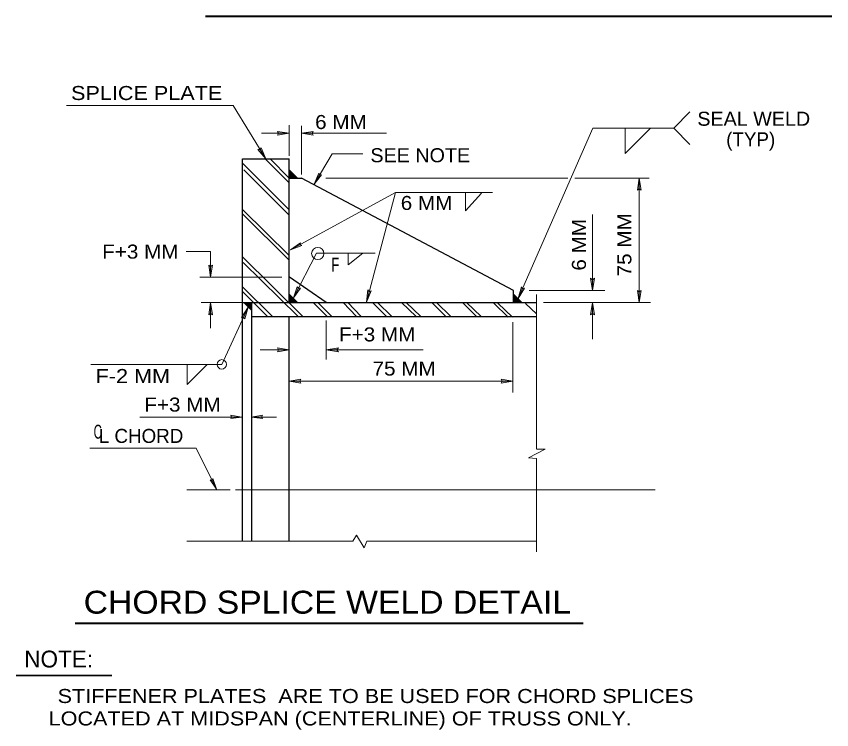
# Model space of a CAD drawing. Extents: x 312601.858 to 312602.699, y 144420.109 to 144420.704.
# Drawn here: x 312602.1021 to 312602.2763, y 144420.3916 to 144420.5441 of the extents above; entities that cross this region are included whole.
import ezdxf
from ezdxf.enums import TextEntityAlignment as Align

# ---------------------------------------------------------------- set-up
doc = ezdxf.new("R2010")
doc.units = 0
doc.header["$LTSCALE"] = 0.0012
doc.linetypes.add('DOT_DASHED', pattern=[7.7, 5, -1.2, 0.3, -1.2])
for name, color, linetype, lineweight in [('1', 7, 'Continuous', 25), ('2', 7, 'Continuous', 13), ('39', 7, 'Continuous', 13)]:
    doc.layers.add(name, color=color, linetype=linetype, lineweight=lineweight)

msp = doc.modelspace()

# ---------------------------------------------------------------- hatches: boundary and pattern name
at = {"layer": '2'}
for points in [[(312602.1604, 144420.5095), (312602.1604, 144420.5113), (312602.1622, 144420.5095)], [(312602.1604, 144420.4829), (312602.1604, 144420.4847), (312602.1622, 144420.4829)], [(312602.2083, 144420.4829), (312602.2083, 144420.4847), (312602.2101, 144420.4829)], [(312602.1524, 144420.4812), (312602.1507, 144420.4829), (312602.1524, 144420.4829)]]:
    msp.add_hatch(color=256, dxfattribs=at).paths.add_polyline_path(points)
at = {"layer": '39'}
for points in [[(312602.1581, 144420.5191), (312602.1579, 144420.5195), (312602.1604, 144420.5191), (312602.1579, 144420.5187)], [(312602.1581, 144420.5191), (312602.1579, 144420.5195), (312602.1604, 144420.5191), (312602.1579, 144420.5187)], [(312602.1653, 144420.5191), (312602.1655, 144420.5187), (312602.163, 144420.5191), (312602.1655, 144420.5195)], [(312602.1542, 144420.5156), (312602.1544, 144420.516), (312602.1554, 144420.5136), (312602.1537, 144420.5156)], [(312602.1669, 144420.5102), (312602.1673, 144420.5102), (312602.1657, 144420.5082), (312602.1667, 144420.5106)], [(312602.2352, 144420.5072), (312602.2348, 144420.5069), (312602.2352, 144420.5095), (312602.2356, 144420.5069)], [(312602.2352, 144420.5072), (312602.2348, 144420.5069), (312602.2352, 144420.5095), (312602.2356, 144420.5069)], [(312602.1627, 144420.4953), (312602.1631, 144420.4951), (312602.1607, 144420.4942), (312602.1628, 144420.4957)], [(312602.1436, 144420.4906), (312602.144, 144420.4909), (312602.1436, 144420.4883), (312602.1432, 144420.4909)], [(312602.1436, 144420.4906), (312602.144, 144420.4909), (312602.1436, 144420.4883), (312602.1432, 144420.4909)], [(312602.2252, 144420.4878), (312602.2256, 144420.4881), (312602.2252, 144420.4855), (312602.2248, 144420.4881)], [(312602.1624, 144420.486), (312602.1628, 144420.486), (312602.1613, 144420.4839), (312602.1621, 144420.4863)], [(312602.2102, 144420.4859), (312602.2107, 144420.486), (312602.2093, 144420.4838), (312602.21, 144420.4863)], [(312602.1775, 144420.4852), (312602.1779, 144420.4854), (312602.1769, 144420.483), (312602.1772, 144420.4856)], [(312602.2352, 144420.4852), (312602.2356, 144420.4855), (312602.2352, 144420.4829), (312602.2348, 144420.4855)], [(312602.1436, 144420.4806), (312602.1432, 144420.4803), (312602.1436, 144420.4829), (312602.144, 144420.4803)], [(312602.2252, 144420.4806), (312602.2248, 144420.4803), (312602.2252, 144420.4829), (312602.2256, 144420.4803)], [(312602.1506, 144420.4798), (312602.1502, 144420.4797), (312602.1516, 144420.4819), (312602.1509, 144420.4794)], [(312602.1581, 144420.4728), (312602.1579, 144420.4732), (312602.1604, 144420.4728), (312602.1579, 144420.4724)], [(312602.1581, 144420.4728), (312602.1579, 144420.4732), (312602.1604, 144420.4728), (312602.1579, 144420.4724)], [(312602.1706, 144420.4728), (312602.1709, 144420.4724), (312602.1683, 144420.4728), (312602.1709, 144420.4732)], [(312602.1627, 144420.4661), (312602.1629, 144420.4657), (312602.1604, 144420.4661), (312602.1629, 144420.4665)], [(312602.1627, 144420.4661), (312602.1629, 144420.4657), (312602.1604, 144420.4661), (312602.1629, 144420.4665)], [(312602.2059, 144420.4661), (312602.2057, 144420.4665), (312602.2082, 144420.4661), (312602.2057, 144420.4657)], [(312602.1481, 144420.4584), (312602.1479, 144420.4588), (312602.1503, 144420.4584), (312602.1479, 144420.4581)], [(312602.1481, 144420.4584), (312602.1479, 144420.4588), (312602.1503, 144420.4584), (312602.1479, 144420.4581)], [(312602.1545, 144420.4584), (312602.1547, 144420.4581), (312602.1523, 144420.4584), (312602.1547, 144420.4588)], [(312602.1439, 144420.4449), (312602.1441, 144420.4453), (312602.1449, 144420.443), (312602.1435, 144420.445)], [(312602.1439, 144420.4449), (312602.1441, 144420.4453), (312602.1449, 144420.443), (312602.1435, 144420.445)]]:
    msp.add_hatch(color=256, dxfattribs=at).paths.add_polyline_path(points)

# ---------------------------------------------------------------- linework, layer by layer
at = {"layer": '1'}
for p, q in [((312602.1604, 144420.4829), (312602.1604, 144420.5136)), ((312602.1604, 144420.5095), (312602.163, 144420.5095)), ((312602.2083, 144420.4855), (312602.163, 144420.5095)), ((312602.1683, 144420.4829), (312602.1605, 144420.4883)), ((312602.2083, 144420.4829), (312602.2083, 144420.4855)), ((312602.1504, 144420.4829), (312602.2132, 144420.4829)), ((312602.1524, 144420.4319), (312602.1524, 144420.4829)), ((312602.1524, 144420.4799), (312602.2132, 144420.4799)), ((312602.1604, 144420.4319), (312602.1604, 144420.4799))]:
    msp.add_line(p, q, dxfattribs=at)
msp.add_lwpolyline([(312602.1504, 144420.4319), (312602.1504, 144420.5136), (312602.1604, 144420.5136)], dxfattribs=at)
at = {"layer": '2', "lineweight": 40}
for p, q in [((312602.1425, 144420.5441), (312602.2763, 144420.5441)), ((312602.1147, 144420.4144), (312602.2232, 144420.4144))]:
    msp.add_line(p, q, dxfattribs=at)
at = {"layer": '2'}
for p, q in [((312602.1484, 144420.525), (312602.1128, 144420.525)), ((312602.1484, 144420.525), (312602.1554, 144420.5136)), ((312602.2426, 144420.5202), (312602.246, 144420.5237)), ((312602.1604, 144420.5143), (312602.1604, 144420.5208)), ((312602.163, 144420.5103), (312602.163, 144420.5207)), ((312602.1545, 144420.5191), (312602.1604, 144420.5191)), ((312602.163, 144420.5191), (312602.1812, 144420.5191)), ((312602.2093, 144420.4838), (312602.2253, 144420.5202)), ((312602.2253, 144420.5202), (312602.2426, 144420.5202)), ((312602.2322, 144420.5148), (312602.2322, 144420.5202)), ((312602.2322, 144420.5148), (312602.2376, 144420.5202)), ((312602.2426, 144420.5202), (312602.246, 144420.5167)), ((312602.1553, 144420.5136), (312602.1604, 144420.5085)), ((312602.1563, 144420.5136), (312602.1604, 144420.5095)), ((312602.1657, 144420.5082), (312602.1696, 144420.5147)), ((312602.1696, 144420.5147), (312602.1761, 144420.5147)), ((312602.1504, 144420.5127), (312602.1604, 144420.5027)), ((312602.1507, 144420.5113), (312602.1604, 144420.5016)), ((312602.1682, 144420.5095), (312602.2199, 144420.5095)), ((312602.2214, 144420.5095), (312602.2373, 144420.5095)), ((312602.2352, 144420.4829), (312602.2352, 144420.5095)), ((312602.1607, 144420.4942), (312602.1831, 144420.5064)), ((312602.1831, 144420.5064), (312602.1769, 144420.483)), ((312602.1831, 144420.5064), (312602.2038, 144420.5064)), ((312602.1981, 144420.5025), (312602.1981, 144420.5064)), ((312602.1981, 144420.5025), (312602.2015, 144420.5063)), ((312602.1504, 144420.5028), (312602.1604, 144420.493)), ((312602.1504, 144420.5019), (312602.1604, 144420.492)), ((312602.2252, 144420.4855), (312602.2252, 144420.5017)), ((312602.1384, 144420.4938), (312602.1436, 144420.4938)), ((312602.1436, 144420.4883), (312602.1436, 144420.4938)), ((312602.1504, 144420.4927), (312602.1633, 144420.4799)), ((312602.1506, 144420.4915), (312602.1623, 144420.4799)), ((312602.1413, 144420.4883), (312602.1588, 144420.4883)), ((312602.1504, 144420.4863), (312602.1568, 144420.4799)), ((312602.1504, 144420.4853), (312602.1558, 144420.4799)), ((312602.2117, 144420.4855), (312602.2278, 144420.4855)), ((312602.2132, 144420.4516), (312602.2132, 144420.4846)), ((312602.1416, 144420.4829), (312602.1504, 144420.4829)), ((312602.1436, 144420.4774), (312602.1436, 144420.4829)), ((312602.1507, 144420.4829), (312602.1524, 144420.4812)), ((312602.1655, 144420.4829), (312602.1685, 144420.4799)), ((312602.1665, 144420.4829), (312602.1695, 144420.4799)), ((312602.1719, 144420.4829), (312602.1748, 144420.4799)), ((312602.1729, 144420.4829), (312602.1758, 144420.4799)), ((312602.1782, 144420.4829), (312602.1812, 144420.4799)), ((312602.1793, 144420.4829), (312602.1823, 144420.4799)), ((312602.1844, 144420.4829), (312602.1875, 144420.4799)), ((312602.1854, 144420.4829), (312602.1885, 144420.4799)), ((312602.1909, 144420.4829), (312602.1939, 144420.4799)), ((312602.1919, 144420.4829), (312602.1949, 144420.4799)), ((312602.1974, 144420.4829), (312602.2004, 144420.4799)), ((312602.1983, 144420.4829), (312602.2014, 144420.4799)), ((312602.2041, 144420.4828), (312602.2072, 144420.4798)), ((312602.205, 144420.4828), (312602.2081, 144420.4798)), ((312602.2109, 144420.4827), (312602.2132, 144420.4805)), ((312602.2147, 144420.4829), (312602.2376, 144420.4829)), ((312602.2252, 144420.4751), (312602.2252, 144420.4829)), ((312602.146, 144420.4697), (312602.1516, 144420.4819)), ((312602.1683, 144420.4707), (312602.1683, 144420.4791)), ((312602.2082, 144420.4637), (312602.2082, 144420.4787)), ((312602.1542, 144420.4728), (312602.1604, 144420.4728)), ((312602.1683, 144420.4728), (312602.189, 144420.4728)), ((312602.118, 144420.4697), (312602.146, 144420.4697)), ((312602.1386, 144420.4654), (312602.1386, 144420.4697)), ((312602.1386, 144420.4654), (312602.1429, 144420.4697)), ((312602.1604, 144420.4661), (312602.2082, 144420.4661)), ((312602.1285, 144420.4584), (312602.1503, 144420.4584)), ((312602.1523, 144420.4584), (312602.1577, 144420.4584)), ((312602.1178, 144420.4518), (312602.1405, 144420.4518)), ((312602.1449, 144420.443), (312602.1405, 144420.4518)), ((312602.2132, 144420.4296), (312602.2132, 144420.4496)), ((312602.1385, 144420.4429), (312602.1478, 144420.4429)), ((312602.1385, 144420.4319), (312602.174, 144420.4319)), ((312602.177, 144420.4319), (312602.2132, 144420.4319))]:
    msp.add_line(p, q, dxfattribs=at)
at = {"layer": '2', "linetype": 'DOT_DASHED'}
msp.add_line((312602.1489, 144420.4429), (312602.2386, 144420.4429), dxfattribs=at)
at = {"layer": '2', "lineweight": 35}
msp.add_line((312602.1021, 144420.4032), (312602.1225, 144420.4032), dxfattribs=at)
at = {"layer": '2'}
for points in [[(312602.1604, 144420.5095), (312602.1604, 144420.5113), (312602.1622, 144420.5095)], [(312602.1604, 144420.4829), (312602.1604, 144420.4847), (312602.1622, 144420.4829)], [(312602.2083, 144420.4829), (312602.2083, 144420.4847), (312602.2101, 144420.4829)], [(312602.1524, 144420.4812), (312602.1507, 144420.4829), (312602.1524, 144420.4829)]]:
    msp.add_lwpolyline(points, close=True, dxfattribs=at)
for points in [[(312602.1613, 144420.4839), (312602.1662, 144420.4935), (312602.1788, 144420.4935)], [(312602.173, 144420.4935), (312602.173, 144420.491), (312602.1761, 144420.4935)], [(312602.2132, 144420.4496), (312602.2115, 144420.4497), (312602.2151, 144420.4516), (312602.2133, 144420.4516)], [(312602.174, 144420.4319), (312602.1748, 144420.4332), (312602.1764, 144420.4305), (312602.177, 144420.4319)]]:
    msp.add_lwpolyline(points, dxfattribs=at)
for centre, radius in [((312602.1665, 144420.4934), 0.0013), ((312602.146, 144420.4697), 0.001005)]:
    msp.add_circle(centre, radius, dxfattribs=at)
at = {"layer": '39'}
for points in [[(312602.1581, 144420.5191), (312602.1579, 144420.5195), (312602.1604, 144420.5191), (312602.1579, 144420.5187)], [(312602.1581, 144420.5191), (312602.1579, 144420.5195), (312602.1604, 144420.5191), (312602.1579, 144420.5187)], [(312602.1653, 144420.5191), (312602.1655, 144420.5187), (312602.163, 144420.5191), (312602.1655, 144420.5195)], [(312602.1542, 144420.5156), (312602.1544, 144420.516), (312602.1554, 144420.5136), (312602.1537, 144420.5156)], [(312602.1669, 144420.5102), (312602.1673, 144420.5102), (312602.1657, 144420.5082), (312602.1667, 144420.5106)], [(312602.2352, 144420.5072), (312602.2348, 144420.5069), (312602.2352, 144420.5095), (312602.2356, 144420.5069)], [(312602.2352, 144420.5072), (312602.2348, 144420.5069), (312602.2352, 144420.5095), (312602.2356, 144420.5069)], [(312602.1627, 144420.4953), (312602.1631, 144420.4951), (312602.1607, 144420.4942), (312602.1628, 144420.4957)], [(312602.1436, 144420.4906), (312602.144, 144420.4909), (312602.1436, 144420.4883), (312602.1432, 144420.4909)], [(312602.1436, 144420.4906), (312602.144, 144420.4909), (312602.1436, 144420.4883), (312602.1432, 144420.4909)], [(312602.2252, 144420.4878), (312602.2256, 144420.4881), (312602.2252, 144420.4855), (312602.2248, 144420.4881)], [(312602.1624, 144420.486), (312602.1628, 144420.486), (312602.1613, 144420.4839), (312602.1621, 144420.4863)], [(312602.2102, 144420.4859), (312602.2107, 144420.486), (312602.2093, 144420.4838), (312602.21, 144420.4863)], [(312602.1775, 144420.4852), (312602.1779, 144420.4854), (312602.1769, 144420.483), (312602.1772, 144420.4856)], [(312602.2352, 144420.4852), (312602.2356, 144420.4855), (312602.2352, 144420.4829), (312602.2348, 144420.4855)], [(312602.1436, 144420.4806), (312602.1432, 144420.4803), (312602.1436, 144420.4829), (312602.144, 144420.4803)], [(312602.2252, 144420.4806), (312602.2248, 144420.4803), (312602.2252, 144420.4829), (312602.2256, 144420.4803)], [(312602.1506, 144420.4798), (312602.1502, 144420.4797), (312602.1516, 144420.4819), (312602.1509, 144420.4794)], [(312602.1581, 144420.4728), (312602.1579, 144420.4732), (312602.1604, 144420.4728), (312602.1579, 144420.4724)], [(312602.1581, 144420.4728), (312602.1579, 144420.4732), (312602.1604, 144420.4728), (312602.1579, 144420.4724)], [(312602.1706, 144420.4728), (312602.1709, 144420.4724), (312602.1683, 144420.4728), (312602.1709, 144420.4732)], [(312602.1627, 144420.4661), (312602.1629, 144420.4657), (312602.1604, 144420.4661), (312602.1629, 144420.4665)], [(312602.1627, 144420.4661), (312602.1629, 144420.4657), (312602.1604, 144420.4661), (312602.1629, 144420.4665)], [(312602.2059, 144420.4661), (312602.2057, 144420.4665), (312602.2082, 144420.4661), (312602.2057, 144420.4657)], [(312602.1481, 144420.4584), (312602.1479, 144420.4588), (312602.1503, 144420.4584), (312602.1479, 144420.4581)], [(312602.1481, 144420.4584), (312602.1479, 144420.4588), (312602.1503, 144420.4584), (312602.1479, 144420.4581)], [(312602.1545, 144420.4584), (312602.1547, 144420.4581), (312602.1523, 144420.4584), (312602.1547, 144420.4588)], [(312602.1439, 144420.4449), (312602.1441, 144420.4453), (312602.1449, 144420.443), (312602.1435, 144420.445)], [(312602.1439, 144420.4449), (312602.1441, 144420.4453), (312602.1449, 144420.443), (312602.1435, 144420.445)]]:
    msp.add_lwpolyline(points, close=True, dxfattribs=at)

# ---------------------------------------------------------------- texts
at = {"layer": '1', "width": 1.1}
msp.add_text('CHORD SPLICE WELD DETAIL', height=0.0049, dxfattribs=at).set_placement((312602.16855, 144420.4164), align=Align.CENTER)
at = {"layer": '2'}
for s, width, p in [('SPLICE PLATE', 1.15, (312602.12995, 144420.5262)), ('6 MM', 1.1, (312602.17145, 144420.52)), ('SEAL WELD', 1.05, (312602.25965, 144420.5207)), ('SEE NOTE', 1.05, (312602.1884, 144420.5129)), ('6 MM', 1.1, (312602.18975, 144420.5027)), ('F+3 MM', 1.1, (312602.1286, 144420.4923)), ('F', 0.7, (312602.17025, 144420.4895)), ('F+3 MM', 1.1, (312602.1792, 144420.4746)), ('75 MM', 1.1, (312602.18495, 144420.4673)), ('F-2 MM', 1.15, (312602.127, 144420.4657)), ('F+3 MM', 1.1, (312602.1376, 144420.4596)), ('C', 0.6, (312602.1195, 144420.4538)), ('STIFFENER PLATES  ARE TO BE USED FOR CHORD SPLICES', 1.15, (312602.17885, 144420.3973)), ('LOCATED AT MIDSPAN (CENTERLINE) OF TRUSS ONLY.', 1.15, (312602.1713, 144420.3925))]:
    msp.add_text(s, height=0.003, dxfattribs=dict(at, width=width)).set_placement(p, align=Align.CENTER)
for s, height, p in [('(TYP)', 0.003, (312602.259, 144420.5163)), ('L CHORD', 0.003, (312602.12875, 144420.4529)), ('NOTE:', 0.0036, (312602.11115, 144420.4049))]:
    msp.add_text(s, height=height, dxfattribs=at).set_placement(p, align=Align.CENTER)
at = {"layer": '2', "width": 1.1}
for s, p in [('75 MM', (312602.2335, 144420.49525)), ('6 MM', (312602.2238, 144420.49525))]:
    msp.add_text(s, height=0.003, rotation=90, dxfattribs=at).set_placement(p, align=Align.CENTER)

doc.saveas('drawing.dxf')
